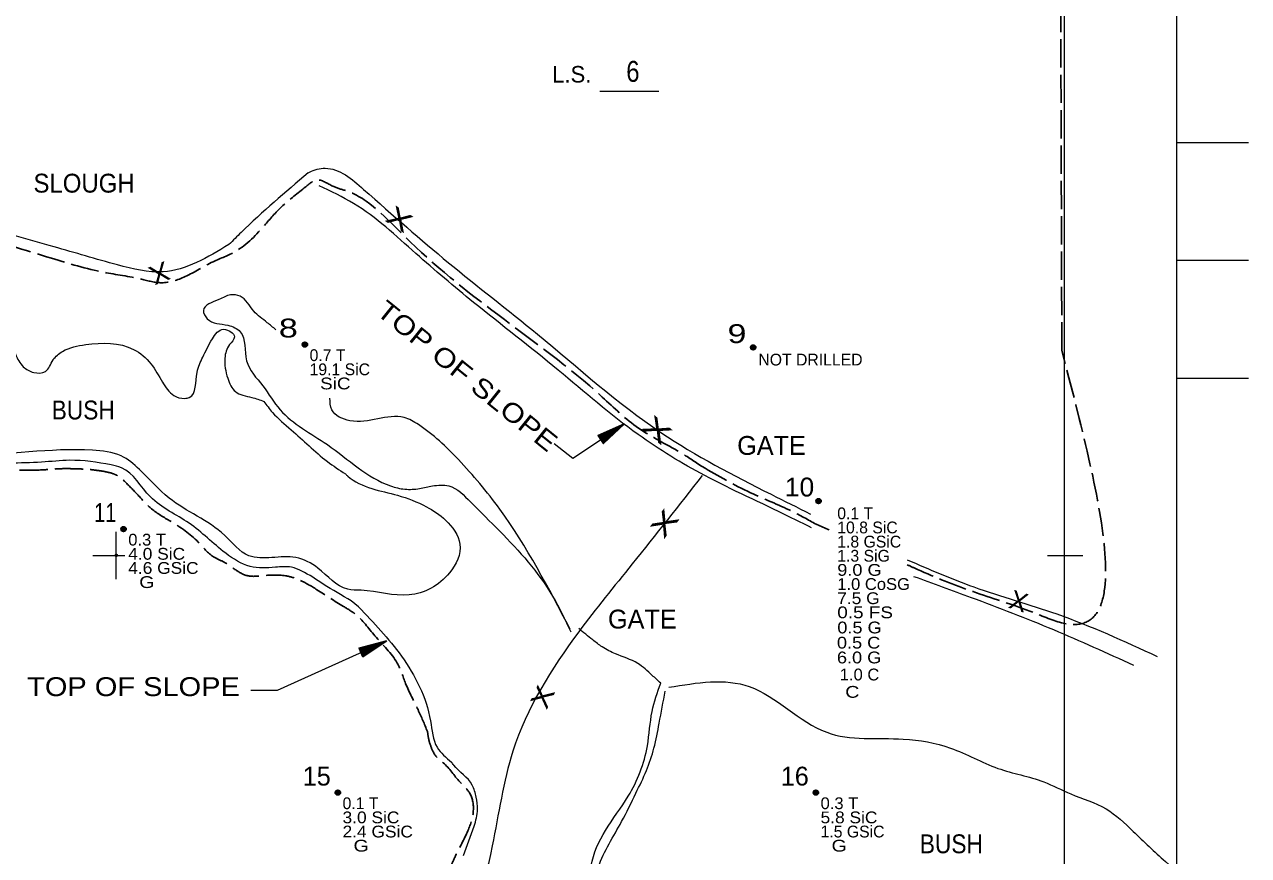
# Model space of a CAD drawing. Extents: x -577 to 499, y -450 to 700.
# Drawn here: x -39 to 480, y -127 to 225 of the extents above; entities that cross this region are included whole.
import ezdxf
from ezdxf.enums import TextEntityAlignment as Align

# ---------------------------------------------------------------- set-up
doc = ezdxf.new("R2010")
doc.units = 0
doc.header["$LTSCALE"] = 2
doc.header["$PDMODE"] = 32
doc.header["$PDSIZE"] = 1
doc.linetypes.add('LONG_DASHED', pattern=[7.5, 6, -1.5])
for name, color, linetype, lineweight in [('1', 7, 'Continuous', 13), ('2', 7, 'Continuous', 35), ('3', 7, 'Continuous', 13), ('4', 7, 'Continuous', 25)]:
    doc.layers.add(name, color=color, linetype=linetype, lineweight=lineweight)

msp = doc.modelspace()

# ---------------------------------------------------------------- linework, layer by layer
at = {"layer": '1'}
for p, q in [((205.122, 196.887), (230.122, 196.887)), ((480.331, 174.973), (449.983, 174.973)), ((480.331, 124.973), (449.983, 124.973)), ((480.331, 74.973), (449.983, 74.973)), ((-0.017, -10.027), (-0.017, 9.973)), ((-10.017, -0.027), (3.662, -0.027)), ((394.983, -0.027), (409.983, -0.027))]:
    msp.add_line(p, q, dxfattribs=at)
for points in [[(449.983, -450.027), (449.983, 399.973), (449.983, 699.973), (-450.017, 699.973), (-450.017, 49.973), (-450.017, -450.027)], [(402.281, -402.333), (402.281, 402.339), (-402.391, 402.339)]]:
    msp.add_lwpolyline(points, dxfattribs=at)
for p in [(0, 0), (0.001, -0.011)]:
    msp.add_point(p, dxfattribs=at)
at = {"layer": '2', "linetype": 'LONG_DASHED', "lineweight": 25}
for p, q in [((401.147, 86.828), (400.063, 399.851)), ((296.892, 13.214), (302.014, 11.045)), ((302.014, 11.045), (302.417, 10.863))]:
    msp.add_line(p, q, dxfattribs=at)
at = {"layer": '2'}
for centre in [(79.982, 89.4), (270.184, 88.196), (297.898, 23.029), (3.055, 11.165), (93.969, -100.599), (296.775, -100.599)]:
    msp.add_circle(centre, 1, dxfattribs=at)
at = {"layer": '2', "linetype": 'LONG_DASHED', "lineweight": 25}
for points in [[(-281.328, 231.83), (-241.679, 217.766), (-223.152, 212.214), (-193.508, 201.481), (-159.789, 189.267), (-142.373, 182.975), (-121.622, 170.021), (-93.831, 153.735), (-76.045, 143.372), (-61.223, 137.08), (-27.503, 125.977), (-5.271, 120.055), (10.663, 117.094), (19.186, 115.613), (29.19, 118.204), (41.048, 124.496), (50.682, 128.937), (63.281, 140.411)], [(63.281, 140.411), (70.598, 148.301), (80.372, 156.328), (84.934, 159.149), (91.884, 156.545), (97.532, 154.592), (122.294, 135.283), (161.826, 102.089), (206.136, 67.159), (221.558, 53.924), (239.152, 43.727), (248.492, 37.653)], [(335.511, -3.987), (339.831, -5.926), (363.49, -15.378), (387.543, -23.649), (400.949, -28.573), (401.147, 86.828)], [(-41.055, 36.19), (-30.058, 36.326), (-23.744, 36.747), (-18.272, 36.747), (-13.011, 36.536), (-7.118, 35.906), (-2.067, 34.855), (0.458, 33.804), (4.036, 30.861), (9.929, 24.764), (14.98, 19.719), (22.977, 14.464), (34.763, 5.635), (41.287, -0.671), (45.496, -2.773), (50.336, -5.927), (55.808, -8.659), (61.491, -8.659), (71.803, -8.659), (77.485, -10.341), (85.062, -14.545), (96.426, -21.693), (101.267, -24.846), (109.685, -34.095), (119.156, -45.657), (122.733, -54.276), (127.995, -65.417), (131.994, -74.666)], [(248.492, 37.653), (269.072, 26.552), (286.506, 18.771), (296.892, 13.214)], [(131.994, -74.666), (132.56, -78.069), (134.001, -82.389), (135.983, -85.629), (138.686, -87.969), (145.714, -96.068), (149.859, -100.748), (151.48, -107.767), (149.138, -116.767), (143.912, -127.386), (142.29, -130.986), (140.669, -134.946), (139.227, -138.906), (138.326, -145.745), (135.443, -150.965), (133.1, -152.585), (126.793, -155.825), (122.288, -158.165), (118.144, -160.324), (115.621, -163.744), (113.639, -166.264), (112.377, -169.864), (112.197, -173.644), (113.098, -176.524), (115.441, -179.403), (118.864, -179.943), (123.91, -179.763), (128.956, -180.123), (133.1, -181.023), (136.524, -181.563), (139.587, -183.003)]]:
    msp.add_spline(points, degree=3, dxfattribs=at)
at = {"layer": '2'}
for points in [[(79.971, 90.287), (80.702, 89.882), (80.853, 89.034), (80.168, 88.506), (79.359, 88.736), (79.073, 89.495), (79.32, 90.056), (79.893, 90.225), (80.567, 89.731), (80.55, 88.989), (80.033, 88.731), (79.511, 88.899), (79.286, 89.545), (79.87, 90.011), (80.308, 89.478), (80.269, 88.995), (79.64, 89.13), (79.786, 89.764), (80.078, 89.214)], [(270.139, 89.02), (270.87, 88.616), (271.021, 87.768), (270.336, 87.24), (269.527, 87.47), (269.241, 88.228), (269.488, 88.79), (270.061, 88.959), (270.735, 88.464), (270.718, 87.723), (270.201, 87.465), (269.679, 87.633), (269.454, 88.279), (270.038, 88.745), (270.476, 88.212), (270.437, 87.728), (269.808, 87.863), (269.954, 88.498), (270.246, 87.948)], [(297.888, 23.957), (298.618, 23.552), (298.77, 22.704), (298.084, 22.176), (297.276, 22.407), (296.989, 23.165), (297.236, 23.726), (297.809, 23.895), (298.483, 23.401), (298.466, 22.659), (297.95, 22.401), (297.427, 22.569), (297.203, 23.215), (297.787, 23.682), (298.225, 23.148), (298.185, 22.665), (297.556, 22.8), (297.702, 23.434), (297.995, 22.884)], [(3.045, 12.052), (3.775, 11.647), (3.927, 10.799), (3.241, 10.271), (2.433, 10.501), (2.146, 11.26), (2.393, 11.821), (2.966, 11.99), (3.64, 11.496), (3.623, 10.754), (3.107, 10.496), (2.584, 10.664), (2.36, 11.31), (2.944, 11.776), (3.382, 11.243), (3.342, 10.76), (2.713, 10.895), (2.859, 11.529), (3.152, 10.979)], [(93.958, -99.712), (94.688, -100.117), (94.84, -100.965), (94.155, -101.493), (93.346, -101.263), (93.059, -100.504), (93.306, -99.943), (93.879, -99.774), (94.553, -100.268), (94.537, -101.01), (94.02, -101.268), (93.497, -101.1), (93.273, -100.454), (93.857, -99.988), (94.295, -100.521), (94.256, -101.004), (93.627, -100.869), (93.773, -100.235), (94.065, -100.785)], [(296.764, -99.712), (297.495, -100.117), (297.646, -100.965), (296.961, -101.493), (296.152, -101.263), (295.866, -100.504), (296.113, -99.943), (296.686, -99.774), (297.36, -100.268), (297.343, -101.01), (296.826, -101.268), (296.304, -101.1), (296.079, -100.454), (296.663, -99.988), (297.101, -100.521), (297.062, -101.004), (296.433, -100.869), (296.579, -100.235), (296.871, -100.785)]]:
    msp.add_spline(points, degree=3, dxfattribs=at)
at = {"layer": '3'}
msp.add_line((102.799, -21.808), (99.653, -19.202), dxfattribs=at)
for points in [[(47.779, 131.805), (19.827, 120.252), (0.549, 123.14), (-26.44, 130.842), (-58.248, 140.47), (-87.165, 153.949), (-137.943, 184.667)], [(97.216, 34.515), (98.149, 33.638), (108.329, 28.351), (119.324, 25.504), (131.539, 20.623), (139.683, 14.929), (145.791, 4.761), (141.312, -7.441), (124.21, -16.795), (103.85, -14.762), (98.149, -14.355), (85.526, -5.407), (76.161, -0.933), (65.981, -0.933), (56.208, -0.12), (46.028, 8.422), (22.411, 24.284), (9.788, 36.485), (2.051, 42.18), (-10.165, 44.62), (-63.507, 42.586), (-85.903, 42.993), (-94.454, 43.4), (-101.376, 48.687), (-108.299, 58.449), (-120.107, 70.65), (-137.617, 80.818), (-171.821, 101.155), (-188.923, 120.271), (-191.366, 129.218), (-187.702, 151.588), (-186.073, 165.417), (-184.037, 175.585)], [(81.345, 162.183), (52.955, 136.933), (47.779, 131.805)], [(81.345, 162.183), (81.976, 162.548), (88.53, 164.184), (104.913, 155.184), (140.957, 124.091), (178.64, 93.816), (231.067, 52.086), (277.761, 25.903), (294.498, 17.535)], [(294.866, 11.736), (285.469, 16.419), (249.642, 33.841), (221.358, 51.263), (187.417, 78.572), (151.59, 107.295), (127.077, 128.013), (100.678, 149.201), (86.065, 156.735)], [(67.639, 95.707), (64.043, 98.673), (58.291, 103.597), (52.539, 109.89), (48.431, 110.437), (43.5, 108.522), (36.926, 103.871), (38.57, 100.314), (47.335, 97.578), (52.539, 94.842), (55.278, 82.531), (62.126, 71.861), (69.521, 61.738), (89.516, 46.964), (116.359, 29.455), (122.385, 28.087), (128.685, 28.36), (134.163, 29.455), (141.011, 29.455), (150.324, 22.615), (162.649, 10.303), (185.11, -17.329), (192.779, -32.376)], [(99.653, -19.202), (87.816, -12.213), (78.653, -6.641), (74.27, -5.049), (67.497, -5.049), (56.74, -4.651), (46.381, 0.92), (30.842, 13.655), (14.507, 24.798), (2.156, 37.135), (-2.227, 38.328), (-19.757, 40.318), (-31.71, 39.522), (-45.256, 39.124), (-61.99, 38.726), (-77.529, 38.328), (-88.684, 38.328), (-95.059, 38.726), (-99.84, 40.716), (-107.809, 48.277), (-120.957, 64.196), (-144.464, 79.318), (-162.791, 88.073), (-182.314, 103.992)], [(-87.25, 88.392), (-86.31, 84.479), (-85.496, 75.531), (-85.496, 69.837), (-83.053, 67.396), (-71.244, 64.549), (-60.657, 65.77), (-54.549, 73.904), (-50.884, 86.512), (-50.477, 98.714), (-49.255, 103.595), (-46.812, 106.035), (-44.776, 104.408), (-43.962, 93.427), (-42.74, 85.292), (-39.483, 80.005), (-35.003, 77.565), (-30.117, 77.971), (-26.86, 82.852), (-22.788, 86.512), (-13.015, 89.36), (7.345, 87.326), (14.674, 81.225), (19.561, 73.497), (24.447, 67.803), (28.926, 66.583), (30.962, 66.99), (34.22, 77.565), (36.663, 84.072), (40.735, 91.8), (45.621, 95.867), (50.1, 92.613), (48.064, 89.36), (46.028, 83.665), (47.25, 75.124), (50.508, 69.43), (57.43, 66.99), (62.592, 65.32)], [(62.592, 65.32), (66.234, 60.644), (74.178, 53.257), (89.516, 39.851), (97.216, 34.515)], [(192.505, -31.282), (162.649, 19.605), (145.119, 40.672), (128.137, 55.446), (122.111, 58.455), (110.881, 57.908), (99.103, 57.087), (91.434, 61.738), (90.601, 66.68)], [(248.573, 33.881), (218.878, -3.63), (196.171, -32.418), (168.223, -83.015), (159.489, -123.144), (145.515, -182.465), (141.148, -219.104), (135.908, -253.127), (131.541, -273.191), (133.288, -297.617), (142.021, -323.788), (169.096, -363.917), (176.083, -379.619), (184.817, -392.705), (185.769, -394.07)], [(335.483, -1.822), (363.775, -13.372), (399, -24.828), (441.597, -42.829)], [(431.605, -46.676), (397.664, -31.609), (362.78, -17.954), (338.339, -9.033)], [(102.799, -21.808), (120.965, -42.742), (133.293, -70.167), (136.094, -81.361), (142.216, -87.704)], [(230.932, -54.116), (227.355, -50.877), (221.177, -45.779), (211.775, -41.755), (206.134, -38.803), (202.105, -35.852), (196.196, -31.023)], [(178.419, -244.641), (184.088, -230.384), (194.184, -205.779), (197.01, -191.661), (201.453, -177.544), (204.279, -165.039), (201.856, -153.342), (201.049, -144.468), (201.453, -131.561), (207.51, -116.636), (217.202, -102.116), (225.278, -80.738), (227.297, -66.217), (230.932, -54.116)], [(234.45, -55.931), (268.542, -55.612), (301.36, -75.026), (333.859, -77.89), (353.932, -81.709), (374.005, -90.301), (393.44, -96.03), (404.91, -101.122), (419.885, -107.487), (431.356, -117.034), (445.056, -129.764), (456.208, -140.903), (460.35, -151.087), (458.438, -161.589), (440.914, -166.681), (401.406, -169.545), (382.607, -167.318), (369.225, -161.907), (361.26, -158.725), (338.957, -158.725), (328.442, -156.497), (305.183, -152.36), (295.625, -147.268), (285.11, -140.585), (275.552, -135.493), (259.621, -138.993), (246.876, -148.223), (237.318, -155.542), (230.308, -161.907), (219.475, -166.999), (211.191, -165.09), (206.731, -160.634), (204.5, -132.31), (214.377, -112.897), (220.431, -100.804), (224.892, -91.256), (228.078, -81.709), (230.308, -71.207), (232.857, -57.522)], [(147.328, -127.258), (151.76, -114.824), (153.277, -107.7), (152.67, -102.548), (151.001, -97.395), (143.111, -88.907), (142.216, -87.704)]]:
    msp.add_spline(points, degree=3, dxfattribs=at)
at = {"layer": '4', "lineweight": 13}
for points in [[(185.705, 47.434), (193.698, 41.292), (215.525, 55.724)], [(57.006, -57.173), (68.38, -57.173), (114.751, -36.199)]]:
    msp.add_lwpolyline(points, dxfattribs=at)
at = {"layer": '4'}
for points in [[(215.525, 55.724), (204.412, 50.774), (206.618, 47.438)], [(114.751, -36.199), (102.993, -39.322), (104.641, -42.967)]]:
    msp.add_lwpolyline(points, close=True, dxfattribs=at)
for points in [[(204.559, 50.729), (215.046, 55.409), (206.664, 47.664), (204.692, 50.609), (214.431, 55.002), (206.731, 47.914), (204.918, 50.578), (213.782, 54.573), (206.773, 48.204), (205.145, 50.47), (213.033, 54.103), (206.865, 48.498), (205.446, 50.408), (212.135, 53.537), (206.885, 48.821), (205.769, 50.311), (211.169, 52.923), (206.939, 49.246), (206.116, 50.257), (210.086, 52.285), (207.084, 49.653), (206.529, 50.219), (208.853, 51.445), (207.207, 50.173)], [(103.131, -39.39), (114.228, -36.435), (104.722, -42.75), (103.243, -39.53), (113.557, -36.738), (104.829, -42.514), (103.461, -39.596), (112.847, -37.059), (104.916, -42.235), (103.668, -39.739), (112.033, -37.405), (105.053, -41.959), (103.956, -39.848), (111.057, -37.821), (105.124, -41.643), (104.259, -39.995), (110.006, -38.273), (105.245, -41.232), (104.593, -40.104), (108.835, -38.731), (105.453, -40.853), (104.995, -40.206), (107.484, -39.365), (105.657, -40.36)]]:
    msp.add_lwpolyline(points, dxfattribs=at)

# ---------------------------------------------------------------- texts
at = {"layer": '1', "width": 0.85}
msp.add_text('6', height=8.89, dxfattribs=at).set_placement((219.146, 200.791), align=Align.CENTER)
at = {"layer": '1'}
msp.add_text('L.S.', height=7, dxfattribs=at).set_placement((193.216, 200.511), align=Align.CENTER)
at = {"layer": '2'}
for s, width, p in [('  8', 1.35, (76.982, 92.4)), ('  9', 1.35, (267.331, 90.03)), (' 10', 1.05, (296.074, 24.977)), (' 11', 0.8, (0.055, 14.165))]:
    msp.add_text(s, height=8, dxfattribs=dict(at, width=width)).set_placement(p, align=Align.RIGHT)
for s, p in [('0.7 T      ', (81.982, 82.4)), ('NOT DRILLED', (272.382, 80.519)), ('19.1 SiC   ', (81.982, 76.4)), ('0.1 T      ', (305.856, 15.341)), ('10.8 SiC   ', (305.856, 9.341)), ('1.8 GSiC   ', (305.856, 3.341)), ('1.3 SiG    ', (305.856, -2.659)), ('0.1 T      ', (95.969, -107.599)), ('1.5 GSiC   ', (298.775, -119.599))]:
    msp.add_text(s, height=5, dxfattribs=at).set_placement(p)
for s, width, p in [('  SiC      ', 1.2, (81.982, 70.4)), ('0.3 T      ', 1.05, (5.055, 4.165)), ('4.0 SiC    ', 1.1, (5.055, -1.835)), ('4.6 GSiC   ', 1.1, (5.055, -7.835)), ('9.0 G      ', 1.15, (305.856, -8.659)), ('  G        ', 1.25, (5.055, -13.835)), ('1.0 CoSG   ', 1.05, (305.856, -14.659)), ('7.5 G      ', 1.1, (305.856, -20.659)), ('0.5 FS     ', 1.2, (305.856, -26.659)), ('0.5 G      ', 1.15, (305.875, -33.077)), ('0.5 C      ', 1.15, (305.716, -39.513)), ('6.0 G      ', 1.15, (305.716, -45.791)), ('1.0 C      ', 1.05, (306.917, -53.01)), ('  C        ', 1.25, (304.572, -60.372)), ('0.3 T      ', 1.05, (298.775, -107.599)), ('3.0 SiC    ', 1.1, (95.969, -113.599)), ('5.8 SiC    ', 1.1, (298.775, -113.599)), ('2.4 GSiC   ', 1.1, (95.969, -119.599)), ('  G        ', 1.25, (95.969, -125.599)), ('  G        ', 1.25, (298.775, -125.599))]:
    msp.add_text(s, height=5, dxfattribs=dict(at, width=width)).set_placement(p)
for s, p in [(' 15', (90.968, -97.599)), (' 16', (293.775, -97.599))]:
    msp.add_text(s, height=8, dxfattribs=at).set_placement(p, align=Align.RIGHT)
at = {"layer": '3'}
for rotation, width, p in [(327.349, 1.45, (117.947, 139.238)), (201.89, 1.15, (16.85, 123.364)), (320.477, 1.65, (227.016, 50.144)), (52.07, 1.6, (235.685, 11.127)), (342.788, 1.05, (381.656, -23.219)), (64.753, 1.25, (184.394, -61.761))]:
    msp.add_text('X', height=8, rotation=rotation, dxfattribs=dict(at, width=width)).set_placement(p, align=Align.CENTER)
at = {"layer": '4'}
for s, width, p in [('SLOUGH', 0.95, (-13.697, 153.832)), ('BUSH', 0.9, (-14.052, 57.638)), ('TOP OF SLOPE', 1.15, (7.268, -59.668)), ('BUSH', 0.9, (354.256, -126.303))]:
    msp.add_text(s, height=8, dxfattribs=dict(at, width=width)).set_placement(p, align=Align.CENTER)
at = {"layer": '4', "width": 1.2}
msp.add_text('TOP OF SLOPE', height=8, rotation=321.117, dxfattribs=at).set_placement((146.371, 72.987), align=Align.CENTER)
at = {"layer": '4'}
for p in [(277.958, 42.621), (223.146, -31.006)]:
    msp.add_text('GATE', height=8, dxfattribs=at).set_placement(p, align=Align.CENTER)

doc.saveas('drawing.dxf')
